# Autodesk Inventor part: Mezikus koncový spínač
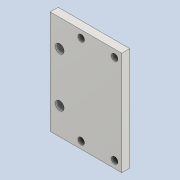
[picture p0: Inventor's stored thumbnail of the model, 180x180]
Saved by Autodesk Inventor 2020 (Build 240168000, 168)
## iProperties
Created: 2025-04
Part Number: Mezikus koncový spínač
Material: Ocel
Document SubType Name: Modeling
Designer: doma
Density: 7.85 g/cm^3
Appearance: Ocel
Author: doma
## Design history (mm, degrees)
sketch "Náčrt1"
  geometry: L1 (-22.5, -32.5)-(22.5, -32.5); L2 (22.5, -32.5)-(22.5, 32.5); L3 (22.5, 32.5)-(-22.5, 32.5); L4 (-22.5, 32.5)-(-22.5, -32.5); L5 (-22.5, -32.5)-(22.5, 32.5); L6 (22.5, -32.5)-(-22.5, 32.5); L7 (-16.5, 15.5)-(-16.5, 0); L8 (-16.5, 0)-(-16.5, -15.5); L9 (-16.5, 0)-(0, 0); L10 (-3, -28)-(18, -28); L11 (18, -28)-(18, 28); L12 (18, 28)-(-3, 28); L13 (-3, 28)-(-3, -28); L14 (-3, -28)-(18, 28); L15 (18, -28)-(-3, 28); L16 (7.5, 0)-(0, 0); C1 r 2.75 at (-16.5, 15.5); C2 r 2.75 at (-16.5, -15.5); 4 further points
  constraints: 32 end point, 5 equal length, 4 coincident, 4 horizontal, 4 midpoint, 2 centre point, 2 perpendicular, 1 collinear, 1 equal radius, 1 vertical
  dimensions: "d0" = 45 distance of L3.end L2.end; "d1" = 65 distance of L2.end L1.end; "d2" = 5.5 diameter of C1; "d3" = 31 distance of L8.end L7.start; "d4" = 6 distance from line of L4 L7.start; "d5" = 21 distance of L11.end L12.end; "d6" = 56 distance of L10.end L11.end; "d7" = 4.5 distance between parallel lines of L2 L11
extrude "Vysunutí1" new body sketch "Náčrt1" distance "d8" = 5; taper "d9" = 0 deg
hole "Díra1" sketch "Náčrt1" diameter "d10" = 4.134; stored, may be unused: countersink angle "d14" = 90 deg, drill point angle "d16" = 118 deg; dims "d11" = 10, "d12" = 4, "d13" = 2, "d15" = 14.2
node "Těleso1"
